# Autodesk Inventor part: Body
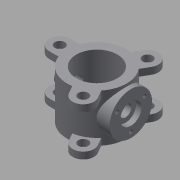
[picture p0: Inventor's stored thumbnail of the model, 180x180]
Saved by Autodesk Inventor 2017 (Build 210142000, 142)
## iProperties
Created: 2011-04
Part Number: Body
Material: Generic
Document SubType Name: Modeling
Designer: Dell
Density: 1 g/cm^3
Appearance: Default
Author: Dell
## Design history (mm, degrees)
sketch "Sketch1"
  geometry: 1 further point
sketch "Sketch2"
  geometry: C1 r 97 at (0, 0); C2 r 140 at (0, 0); 1 further point
  constraints: 2 centre point, 1 coincident
  dimensions: "d0" = 194 diameter of C1; "d1" = 280 diameter of C2
extrude "Extrusion1" new body sketch "Sketch2" stored distance "d2" = 225; taper "d3" = 0 deg
workplane "Work Plane1"
sketch "Sketch3"
  geometry: L1 (-140, 112.5)-(140, 112.5) reference; C1 r 100 at (0, 0); 1 further point
  constraints: 1 centre point, 1 coincident
  dimensions: "d5" = 200 diameter of C1; "d7" = 112.5 distance from line of point (0, 0) L1 (derived)
extrude "Extrusion2" join sketch "Sketch3" stored distance "d8" = 225; taper "d9" = 0 deg
hole "Hole1" diameter "d12" = 56; stored, may be unused: countersink angle "d16" = 90 deg, drill point angle "d18" = 118 deg; dims "d13" = 6, "d14" = 100, "d15" = 25, "d17" = 428.75, "d39" = 10, "d40" = 10
workplane "Work Plane2"
sketch "Sketch4"
  geometry: C1 r 37.5 at (0, 0); C2 r 28 at (0, 0); 1 further point
  constraints: 2 centre point, 1 coincident
  dimensions: "d20" = 75 diameter of C1; "d37" = 56 diameter of C2
sketch "Sketch5"
  geometry: L1 (130.767, -50)-(175, -50); L2 (175, 50)-(130.767, 50); C1 r 23.5 at (175, 0); A1 r 50 centre (175, 0) between (175, -50) and (175, 50); A2 r 140 centre (0, 0) between (130.767, -50) and (130.767, 50); 1 further point
  constraints: 4 end point, 4 point on circle, 3 centre point, 2 coincident
  dimensions: "d29" = 50 radius of A1 (derived); "d30" = 47 diameter of C1 (derived); "d31" = 175 distance of A1.centre point (0, 0)
extrude "Extrusion4" join sketch "Sketch5" distance "d32" = 32; taper "d33" = 0 deg
pattern_circular "Circular Pattern1" dims angle "d35" = 360 deg
mirror "Mirror1"
extrude "Extrusion5" join sketch "Sketch4" stored distance "d38" = 32; taper "d41" = 0 deg; dims "d13" = 6
sketch "Sketch6"
  geometry: C1 r 50 at (0, 0); C2 r 100 at (0, 0); 3 further points
  constraints: 2 centre point, 4 other
  dimensions: "d44" = 75 distance of point (75, 0) C1.centre; "d45" = 360 deg dimension on C1.centre point (75, 0) (derived)
hole "Hole2" sketch "Sketch6" at (-37.5, 64.952) diameter "d46" = 18.376; stored, may be unused: countersink angle "d50" = 90 deg, drill point angle "d52" = 0 deg; dims "d47" = 15, "d48" = 4, "d49" = 2, "d51" = 15
pattern_circular "Circular Pattern2" dims angle "d54" = 360 deg
body "Solid1"
other parameters: "d19" = -325
